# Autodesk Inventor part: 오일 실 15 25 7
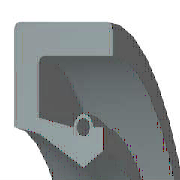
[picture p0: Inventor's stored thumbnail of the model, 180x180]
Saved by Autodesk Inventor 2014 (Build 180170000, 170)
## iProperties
Created: 2012-02
Part Number: 오일 실 15 25 7
Material: 고무
Description: 오일-실
Document SubType Name: Modeling
Standard: KS B 2804
Designer: mduedu
Standards Organization: KS
Language: ko-KR
Size Designation: S - 15 25 7
Categories: <MemberInstance><Categories><Category DisplayName="샤프트 부품" InternalName="7f7aeb1f-a693-4053-b835-cee3144e0d98" Mnemonic="SHFT"><Category DisplayName="실링" Intern
Density: 0.93 g/cm^3
Appearance: Rubber - Black - Version 1.1
IsCustomPart: 1
Author: mduedu
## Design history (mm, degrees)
revolve "본체" stored, may be unused: angle "d17" = 90 deg
revolve "스프링1" stored, may be unused: angle "d18" = 90 deg
body "Solid1"
sketch "스케치1"
  geometry: L1 (0, 12.5)-(7, 12.5); L2 (7, 12.5)-(7, 11.25); L3 (7, 11.25)-(1.75, 11.25); L4 (0, 12.5)-(0, 9.6); L5 (0, 9.6)-(1.75, 9.25); L6 (1.75, 9.25)-(4.9, 7.5); L7 (4.9, 7.5)-(0, 7.5); L8 (6.3, 8.375)-(6.3, 9.6); L9 (0, 0)-(9.586, 0) reference; L10 (4.9, 7.5)-(6.3, 8.375); L11 (0, 18)-(0, -3) reference; L12 (-1.917, 0)-(11.503, 0) reference; L13 (4.2, 9.6)-(1.75, 10.09); L14 (1.75, 10.09)-(1.75, 11.25); L15 (6.3, 9.6)-(5.6, 9.6); C1 r 0.455 at (4.9, 9.6); A1 r 0.7 centre (4.9, 9.6) between (5.6, 9.6) and (4.2, 9.6)
  constraints: 26 end point, 5 horizontal alignment, 4 perpendicular, 2 centre point, 2 collinear, 2 horizontal, 2 parallel, 2 point on circle, 2 point on line, 2 vertical alignment, 1 coincident
  dimensions: "d0" = 25 diameter of L1 L9 (= SD2); "d1" = 16.75 diameter of L8.start L9 (= ABDM); "d2" = 1.25 distance of L1.end L2.end (computed from SD); "d3" = 0.91 diameter of C1 (= SPDI); "d4" = 1.4 diameter of A1 (= SPDA); "d5" = 15 diameter of L6.end L9 (= NND); "d6" = 18.5 diameter of L5.end L9 (= TKDM); "d7" = 19.2 diameter of L4.end L9 (= HLDM); "d8" = 4.9 distance from line of C1.centre L4 (= SPDST); "d9" = 6.3 distance between parallel lines of L8 L4 (= SDI); "d10" = 7 distance between parallel lines of L2 L4 (= SWDT); "d12" = 1.75 distance between parallel lines of L14 L4 (= SD)
fillet "모깎기1" dims "d11" = 0.3 (= RR)
other parameters: "SD2" = 25 [user parameter; used in 1 equation term], "SWDT" = 7 [user parameter; used in 1 equation term], "RR" = 0.3 [user parameter; used in 1 equation term], "SD" = 1.75 [user parameter; used in 2 equation terms], "NND" = 15 [user parameter; used in 1 equation term], "SPDA" = 1.4 [user parameter; used in 1 equation term], "SPDI" = 0.91 [user parameter; used in 1 equation term], "TKDM" = 18.5 [user parameter; used in 1 equation term], "HLDM" = 19.2 [user parameter; used in 1 equation term], "ABDM" = 16.75 [user parameter; used in 1 equation term], "SDI" = 6.3 [user parameter; used in 1 equation term], "SPDST" = 4.9 [user parameter; used in 1 equation term], "d13" = 0, "d14" = 0, "d15" = 0, "LAB" = 0.35 [user parameter]
